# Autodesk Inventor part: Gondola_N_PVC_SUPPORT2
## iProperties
Shininess: 64.0
Length Units: 11272
Angle Units: 11279
Time Units: 11290
Mass Units: 11286
Length Display Precision: 3
Angle Display Precision: 2
Compacted: True
Part Number: Gondola_N_PVC_SUPPORT2
Document SubType Name: Modeling
Created: 2004-12
Designer: John Blackburn
Material: PVC-Piping
Manufacturer: Standard
Standards Organization: Custom
Density: 0.0
Volumn: 0.0
Area: 0.0
PropertySet Name: Model Information
Control State: 0
Master: False
Checked Out: False
Author: John Blackburn
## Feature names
1. Extrusion1
2. Hole1
3. Hole2
4. Hole3
